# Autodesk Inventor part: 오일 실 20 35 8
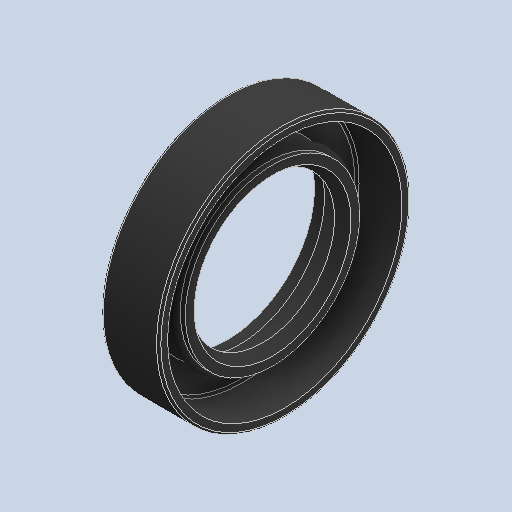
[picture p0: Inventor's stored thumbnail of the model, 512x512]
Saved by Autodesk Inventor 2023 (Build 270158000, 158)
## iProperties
Created: 2026-03
Part Number: 오일 실 20 35 8
Material: 고무
Description: 오일-실
Document SubType Name: Modeling
Designer: 4강의실
Density: 0.93 g/cm^3
Appearance: 기본값
Author: jhkim
Sending System: Autodesk Inventor 2026
Preprocessor: ST-DEVELOPER v20.1
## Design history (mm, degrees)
feature "Solid1"
node "솔리드1"
